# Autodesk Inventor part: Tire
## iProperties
Author: Administrator
Created: 2001-04
Part Number: Tire
Document SubType Name: Modeling
Designer: Administrator
Control State: 0
Master: False
Checked Out: False
PropertySet Name: Design Tracking Control
Shininess: 5.0
PropertySet Name: _Private Model Information
Density: 0.0
Volumn: 0.0
Area: 0.0
PropertySet Name: Model Information
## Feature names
1. Revolution1
